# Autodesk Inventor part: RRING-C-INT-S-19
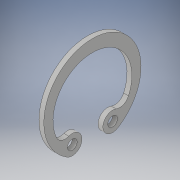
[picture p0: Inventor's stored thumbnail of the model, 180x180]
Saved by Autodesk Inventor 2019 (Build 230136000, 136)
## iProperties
Created: 2022-11
Part Number: RRING-C-INT-S-19
Material: Generic
Catalog Web Link: www.cadenas.de
Description: RRING_C_INT-Retaining Rings - C  (Internal)
Vendor: MISUMI
Document SubType Name: Modeling
Designer: psAdmin
Manufacturer: MISUMI
Mass: 0.110311 g
Surface Area: 3.39751 cm^2
Volume: 0.110311 cm^3
Density: 1 g/cm^3
Appearance: PSOLRGB-175-175-175
Category: PARTsolutions
Company: MISUMI
Title: RRING-C-INT-S-19
Author: Cadenas PARTsolutions
Comments: Retaining Rings - C  (Internal)
PSOL_IDENT_0: {$CADENAS_DATA/23d-libs/misumi/metric/accessories/rring_c_int.prj},180 {VTYP=3D},{NB=RRING-C-INT-S-1
PSOL_IDENT_1: 9},{LINA=RRING-C-INT-S-19},{NN=RRING_C_INT},{DATE=30.06.2021 13:30:10},{GEOMDATE=05.03.2015 00:00:00
PSOL_IDENT_2: },{VERSION=},{LINEID=90},{WBVAR=MAT},{WBNUMERIC=}  {NB=RRING-C-INT-S-19},{LINA=RRING-C-INT-S-19},{KT=
PSOL_IDENT_3: DUMMY},{PN=RRING-C-INT-S-19},{TYPE=RRING-C-INT},{MAT=-S},{HARD=36~44HRC},{NO=19},{DD3=20.5},{DD3TOL=
PSOL_IDENT_4: +0.2/-0.2},{TT=1.00},{TTTOL=+0.05/-0.05},{BB=2.5},{AA=4.0},{DD0=2.0},{DD4=11},{DD1=19},{DD2=20.0},{D
PSOL_IDENT_5: D2TOL=+0.21/0},{MM=1.15},{MMTOL=+0.14/0},{NN=1.5},{A2=8.30}
NB: RRING-C-INT-S-19
NN: 1.5
NT: Retaining Rings - C  (Internal)
NBSYN: $PN.
LINA: RRING-C-INT-S-19
CATALOG: Misumi
PN: RRING-C-INT-S-19
MAT: 304 Stainless Steel-CSP
HARD: 36~44HRC
NO: 19
DD3: 20.5
DD3TOL: +0.2/-0.2
TT: 1
TTTOL: +0.05/-0.05
BB: 2.5
AA: 4
DD0: 2
DD4: 11
DD1: 19
DD2: 20
DD2TOL: +0.21/0
MM: 1.15
MMTOL: +0.14/0
SUPPLIER: MISUMI
ARTICLENO: RRING-C-INT-S-19
BOMINFO: RRING-C-INT-S-19
CREATOR: CADENAS GmbH
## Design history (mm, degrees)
sketch "Sketch_3"
  geometry: C1 r 1 at (-6.839, -4.15); C2 r 1 at (-6.839, 4.15); A1 r 10 centre (0, 0) between (-8.549, -5.188) and (-8.549, 5.188); A2 r 2 centre (-6.839, 4.15) between (-8.549, 5.188) and (-7.416, 2.235); A3 r 2 centre (-6.839, 4.15) between (-7.416, 2.235) and (-4.975, 4.874); A4 r 2 centre (-3.111, 5.598) between (-3.922, 7.426) and (-4.975, 4.874); A5 r 8.125 centre (-0.625, 0) between (-3.922, -7.426) and (-3.922, 7.426); A6 r 2 centre (-3.111, -5.598) between (-4.975, -4.874) and (-3.922, -7.426); A7 r 2 centre (-6.839, -4.15) between (-4.975, -4.874) and (-7.416, -2.235); A8 r 2 centre (-6.839, -4.15) between (-7.416, -2.235) and (-8.549, -5.188); 2 further points
  constraints: 16 point on circle, 10 centre point
extrude "Extrusion1" join sketch "Sketch_3" stored distance "d0" = 1; taper "d1" = 0 deg
node "rr_XY"
node "rr_YZ"
node "rr_ZX"
node "rr_X"
node "rr_Y"
node "rr_Z"
node "rr_Center"
body "Solid1"
other parameters: "d2" = 0
